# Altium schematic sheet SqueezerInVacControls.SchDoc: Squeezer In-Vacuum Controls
size B; Organization: LIGO Laboratory; Address1: California Institute of Technology; Address2: Massachusetts Institute of Technology; SheetNumber: 29; SheetTotal: 37; DrawnBy: R.  Abbott; Engineer: R.  Abbott; PageSetup: Record=PageOptions¦CenterHorizontal=True¦CenterVertical=True¦PrintScale=1.09¦XCorrection=1.00¦YCorrection=1.00¦PrintKind=0¦BorderSize=5000000¦LeftOffset=0¦BottomOffset=0¦Orientation=2¦PaperLength=1000¦PaperWidth=1000¦Scale=100¦PaperSource=7¦PrintQuality=-4¦MediaType=1¦DitherType=10¦PaperKind=11x17¦PrintScaleMode=1
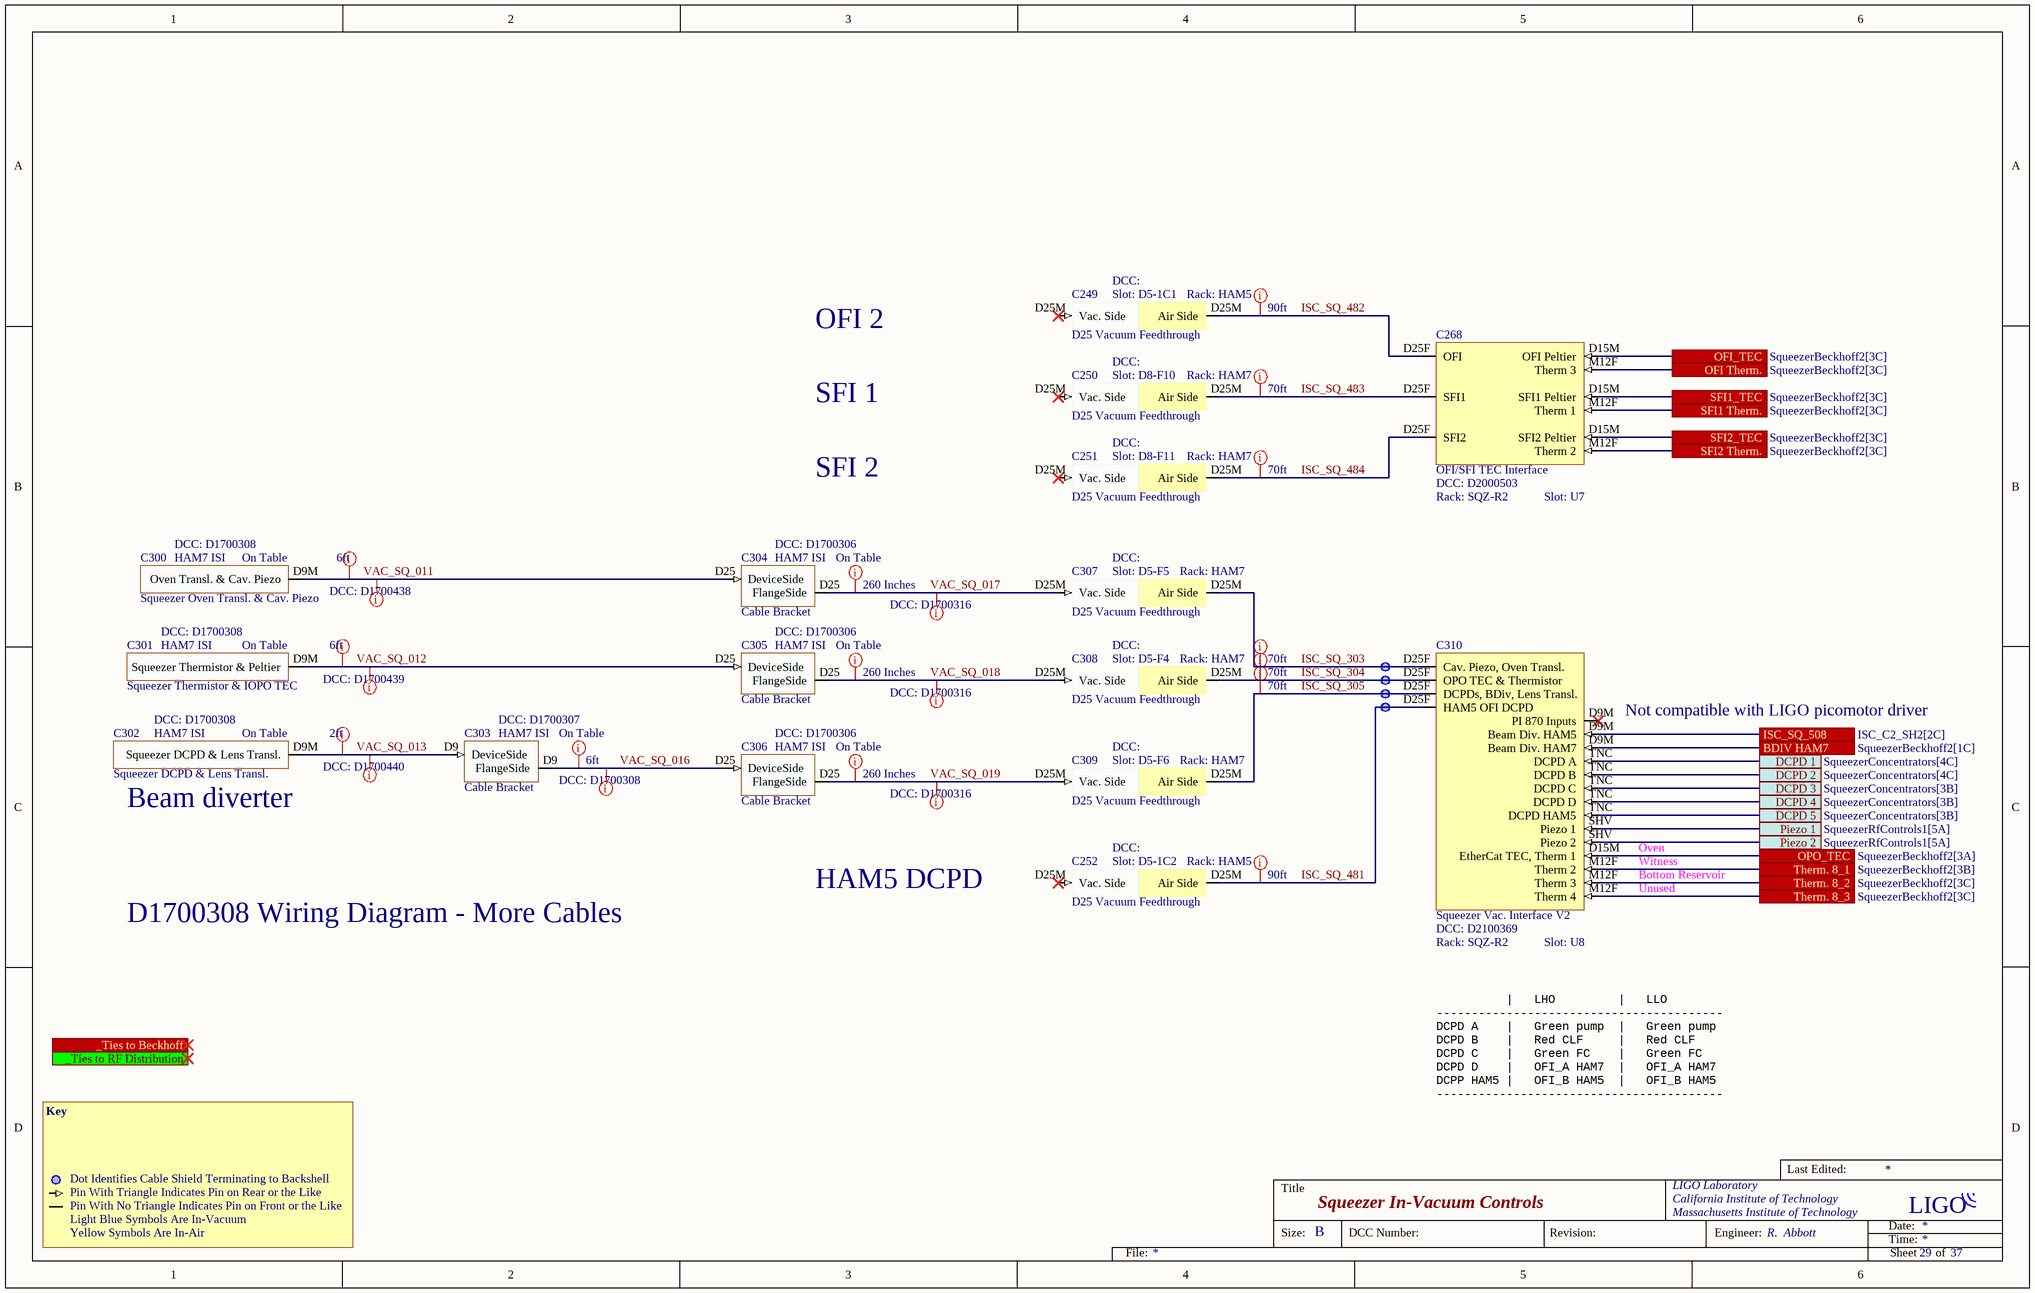
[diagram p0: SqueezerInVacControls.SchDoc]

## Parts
C249  D25 Vacuum Feedthrough  Rack: HAM5  Slot: D5-1C1
C250  D25 Vacuum Feedthrough  Rack: HAM7  Slot: D8-F10
C251  D25 Vacuum Feedthrough  Rack: HAM7  Slot: D8-F11
C252  D25 Vacuum Feedthrough  Rack: HAM5  Slot: D5-1C2
C268  OFI/SFI TEC Interface  DCC: D2000503  Rack: SQZ-R2  Slot: U7
C300  Squeezer Oven Transl. & Cav. Piezo  DCC: D1700308  Rack: HAM7 ISI  Slot: On Table
C301  Squeezer Thermistor & IOPO TEC  DCC: D1700308  Rack: HAM7 ISI  Slot: On Table
C302  Squeezer DCPD & Lens Transl.  DCC: D1700308  Rack: HAM7 ISI  Slot: On Table
C303  Cable Bracket  DCC: D1700307  Rack: HAM7 ISI  Slot: On Table
C304  Cable Bracket  DCC: D1700306  Rack: HAM7 ISI  Slot: On Table
C305  Cable Bracket  DCC: D1700306  Rack: HAM7 ISI  Slot: On Table
C306  Cable Bracket  DCC: D1700306  Rack: HAM7 ISI  Slot: On Table
C307  D25 Vacuum Feedthrough  Rack: HAM7  Slot: D5-F5
C308  D25 Vacuum Feedthrough  Rack: HAM7  Slot: D5-F4
C309  D25 Vacuum Feedthrough  Rack: HAM7  Slot: D5-F6
C310  Squeezer Vac. Interface V2  DCC: D2100369  Rack: SQZ-R2  Slot: U8

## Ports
_Ties to Beckhoff, _Ties to RF Distribution, BDIV HAM7 (see SqueezerBeckhoff2[1C]), DCPD 1 (see SqueezerConcentrators[4C]), DCPD 2 (see SqueezerConcentrators[4C]), DCPD 3 (see SqueezerConcentrators[3B]), DCPD 4 (see SqueezerConcentrators[3B]), DCPD 5 (see SqueezerConcentrators[3B]), ISC_SQ_508 (see ISC_C2_SH2[2C]), OFI Therm. (see SqueezerBeckhoff2[3C]), OFI_TEC (see SqueezerBeckhoff2[3C]), OPO_TEC (see SqueezerBeckhoff2[3A]), Piezo 1 (see SqueezerRfControls1[5A]), Piezo 2 (see SqueezerRfControls1[5A]), SFI1 Therm. (see SqueezerBeckhoff2[3C]), SFI1_TEC (see SqueezerBeckhoff2[3C]), SFI2 Therm. (see SqueezerBeckhoff2[3C]), SFI2_TEC (see SqueezerBeckhoff2[3C]), Therm. 8_1 (see SqueezerBeckhoff2[3B]), Therm. 8_2 (see SqueezerBeckhoff2[3C]), Therm. 8_3 (see SqueezerBeckhoff2[3C])

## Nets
BDIV HAM7: C310.D9M(Beam_Div._HAM7) ; port BDIV HAM7
DCPD 1: C310.TNC(DCPD_A) ; port DCPD 1
DCPD 2: C310.TNC(DCPD_B) ; port DCPD 2
DCPD 3: C310.TNC(DCPD_C) ; port DCPD 3
DCPD 4: C310.TNC(DCPD_D) ; port DCPD 4
DCPD 5: C310.TNC(DCPD_HAM5) ; port DCPD 5
ISC_SQ_303: C307.D25M(Air_Side) C310.D25F(Cav._Piezo,_Oven_Transl.)
ISC_SQ_304: C308.D25M(Air_Side) C310.D25F(OPO_TEC_&_Thermistor)
ISC_SQ_305: C309.D25M(Air_Side) C310.D25F(DCPDs,_BDiv,_Lens_Transl.)
ISC_SQ_481: C252.D25M(Vac._Side) C310.D25F(HAM5_OFI_DCPD)
ISC_SQ_482: C249.D25M(Vac._Side) C268.D25F(OFI)
ISC_SQ_483: C250.D25M(Vac._Side) C268.D25F(SFI1)
ISC_SQ_484: C251.D25M(Vac._Side) C268.D25F(SFI2)
ISC_SQ_508: C310.D9M(Beam_Div._HAM5) ; port ISC_SQ_508
OFI Therm.: C268.M12F(Therm_3) ; port OFI Therm.
OFI_TEC: C268.D15M(OFI_Peltier) ; port OFI_TEC
OPO_TEC: C310.D15M(EtherCat_TEC,_Therm_1) ; port OPO_TEC
Piezo 1: C310.SHV(Piezo_1) ; port Piezo 1
Piezo 2: C310.SHV(Piezo_2) ; port Piezo 2
SFI1 Therm.: C268.M12F(Therm_1) ; port SFI1 Therm.
SFI1_TEC: C268.D15M(SFI1_Peltier) ; port SFI1_TEC
SFI2 Therm.: C268.M12F(Therm_2) ; port SFI2 Therm.
SFI2_TEC: C268.D15M(SFI2_Peltier) ; port SFI2_TEC
Therm. 8_1: C310.M12F(Therm_2) ; port Therm. 8_1
Therm. 8_2: C310.M12F(Therm_3) ; port Therm. 8_2
Therm. 8_3: C310.M12F(Therm_4) ; port Therm. 8_3
VAC_SQ_011: C300.D9M(Oven_Transl._&_Cav._Piezo) C304.D25(DeviceSide)
VAC_SQ_012: C301.D9M(Squeezer_Thermistor_&_Peltier) C305.D25(DeviceSide)
VAC_SQ_013: C302.D9M(Squeezer_DCPD_&_Lens_Transl.) C303.D9(DeviceSide)
VAC_SQ_016: C303.D9(FlangeSide) C306.D25(DeviceSide)
VAC_SQ_017: C304.D25(FlangeSide) C307.D25M(Vac._Side)
VAC_SQ_018: C305.D25(FlangeSide) C308.D25M(Vac._Side)
VAC_SQ_019: C306.D25(FlangeSide) C309.D25M(Vac._Side)

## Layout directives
DCC: D1700438: VAC_SQ_011
DCC: D1700439: VAC_SQ_012
DCC: D1700440: VAC_SQ_013
DCC: D1700308: VAC_SQ_016
Length: 70ft: ISC_SQ_303, ISC_SQ_304, ISC_SQ_305, ISC_SQ_483, ISC_SQ_484
Length: 260 Inches: VAC_SQ_017, VAC_SQ_018, VAC_SQ_019
DCC: D1700316: VAC_SQ_017, VAC_SQ_018, VAC_SQ_019
Length: 6ft: VAC_SQ_011, VAC_SQ_012, VAC_SQ_016
Length: 2ft: VAC_SQ_013
Length: 90ft: ISC_SQ_481, ISC_SQ_482

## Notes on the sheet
- OFI 2
- SFI 1
- SFI 2
- (near C310) Not compatible with LIGO picomotor driver
- (near C302) Beam diverter
- HAM5 DCPD
- Oven
- Witness
- Bottom Reservoir
- Unused
- D1700308 Wiring Diagram - More Cables
- |   LHO         |   LLO
  -----------------------------------------
  DCPD A    |   Green pump  |   Green pump
  DCPD B    |   Red CLF     |   Red CLF
  DCPD C    |   Green FC    |   Green FC
  DCPD D    |   OFI_A HAM7  |   OFI_A HAM7
  DCPP HAM5 |   OFI_B HAM5  |   OFI_B HAM5
  -----------------------------------------
- Key
- Dot Identifies Cable Shield Terminating to Backshell
- Pin With Triangle Indicates Pin on Rear or the Like
- Pin With No Triangle Indicates Pin on Front or the Like
- Light Blue Symbols Are In-Vacuum
- Yellow Symbols Are In-Air

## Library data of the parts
C249-C252 C307-C309 = VacFeedD25: Serial: Sxxxxxxx; System: ISC
C268 = OFI/SFI TEC Interface: Serial: Sxxxxxxx; System: ISC
C300 = Squeezer Oven Transl. & Cav. Piezo: Serial: Sxxxxxxx; System: ISC
C301 = Squeezer Thermistor & Peltier: Serial: Sxxxxxxx; System: ISC
C302 = Squeezer DCPD & Lens Transl.: Serial: Sxxxxxxx; System: ISC
C303 = CabBracket_D9: Serial: Sxxxxxxx; System: ISC
C304-C306 = CabBracket_D25: Serial: Sxxxxxxx; System: ISC
C310 = Squeezer Vac. Interface V2: Serial: Sxxxxxxx; System: ISC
